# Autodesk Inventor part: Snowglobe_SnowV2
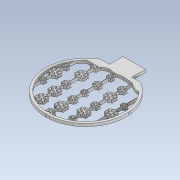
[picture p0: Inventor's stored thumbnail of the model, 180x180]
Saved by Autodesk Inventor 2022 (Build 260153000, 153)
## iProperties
Created: 2021-12
Part Number: Snowglobe_SnowV2
Material: Generic
Document SubType Name: Modeling
Designer: allis
Density: 1 g/cm^3
Appearance: Default
Author: allis
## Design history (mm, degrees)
sketch "Sketch1"
  geometry: L1 (69.69, -82.041)-(70.035, -82.041); L2 (70.035, -82.041)-(70.342, -82.04); L3 (70.342, -82.04)-(70.65, -82.042); L4 (70.65, -82.042)-(70.75, -82.042); L5 (70.75, -82.042)-(70.863, -82.053); L6 (70.863, -82.053)-(70.908, -81.948); L7 (70.908, -81.948)-(70.948, -81.852); L8 (70.948, -81.852)-(70.862, -81.774); L9 (70.862, -81.774)-(70.814, -81.698); L10 (70.814, -81.698)-(70.785, -81.652); L11 (70.785, -81.652)-(70.743, -81.601); L12 (70.743, -81.601)-(70.695, -81.581); L13 (70.695, -81.581)-(70.349, -81.437); L14 (70.349, -81.437)-(70.061, -81.177); L15 (70.061, -81.177)-(69.69, -81.047); L16 (69.69, -81.047)-(69.69, -81.384); L17 (69.69, -81.384)-(69.69, -81.69); L18 (69.69, -81.69)-(69.69, -82.041); L19 (68.821, -81.037)-(68.526, -81.201); L20 (68.526, -81.201)-(68.245, -81.343); L21 (68.245, -81.343)-(67.978, -81.507); L22 (67.978, -81.507)-(67.63, -81.722); L23 (67.63, -81.722)-(67.634, -81.73); L24 (67.634, -81.73)-(67.657, -82.138); L25 (67.657, -82.138)-(67.658, -82.161); L26 (67.658, -82.161)-(67.687, -82.182); L27 (67.687, -82.182)-(67.732, -82.241); L28 (67.732, -82.241)-(68.062, -82.066); L29 (68.062, -82.066)-(68.443, -82.153); L30 (68.443, -82.153)-(68.821, -82.114); L31 (68.821, -82.114)-(68.821, -81.755); L32 (68.821, -81.755)-(68.821, -81.42); L33 (68.821, -81.42)-(68.821, -81.037); L34 (49.276, -9.775)-(49.276, -10.064); L35 (49.276, -10.064)-(49.288, -10.345); L36 (49.288, -10.345)-(49.272, -10.625); L37 (49.272, -10.625)-(49.262, -10.794); L38 (49.262, -10.794)-(49.342, -10.91); L39 (49.342, -10.91)-(49.465, -10.969); L40 (49.465, -10.969)-(49.795, -11.129); L41 (49.795, -11.129)-(50.076, -11.383); L42 (50.076, -11.383)-(50.462, -11.484); L43 (50.462, -11.484)-(50.462, -11.072); L44 (50.462, -11.072)-(50.458, -10.665); L45 (50.458, -10.665)-(50.464, -10.259); L46 (50.464, -10.259)-(50.465, -10.149); L47 (50.465, -10.149)-(50.439, -10.058); L48 (50.439, -10.058)-(50.341, -10.012); L49 (50.341, -10.012)-(50.018, -9.862); L50 (50.018, -9.862)-(49.715, -9.629); L51 (49.715, -9.629)-(49.276, -9.775); L52 (52.577, -9.74)-(52.3, -9.754); L53 (52.3, -9.754)-(52.051, -9.674); L54 (52.051, -9.674)-(51.818, -9.821); L55 (51.818, -9.821)-(51.677, -9.909); L56 (51.677, -9.909)-(51.538, -9.999); L57 (51.538, -9.999)-(51.391, -10.074); L58 (51.391, -10.074)-(51.329, -10.106); L59 (51.329, -10.106)-(51.31, -10.145); L60 (51.31, -10.145)-(51.31, -10.203); L61 (51.31, -10.203)-(51.309, -10.635); L62 (51.309, -10.635)-(51.309, -11.067); L63 (51.309, -11.067)-(51.309, -11.497); L64 (51.309, -11.497)-(51.377, -11.501)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; 1 further point
  constraints: 15 other
extrude "Extrusion1" new body sketch "Sketch1" distance "d0" = 3.175; taper "d1" = 0 deg
feature "Move Body1"
body "Solid1"
other parameters: "d2" = 90 deg
